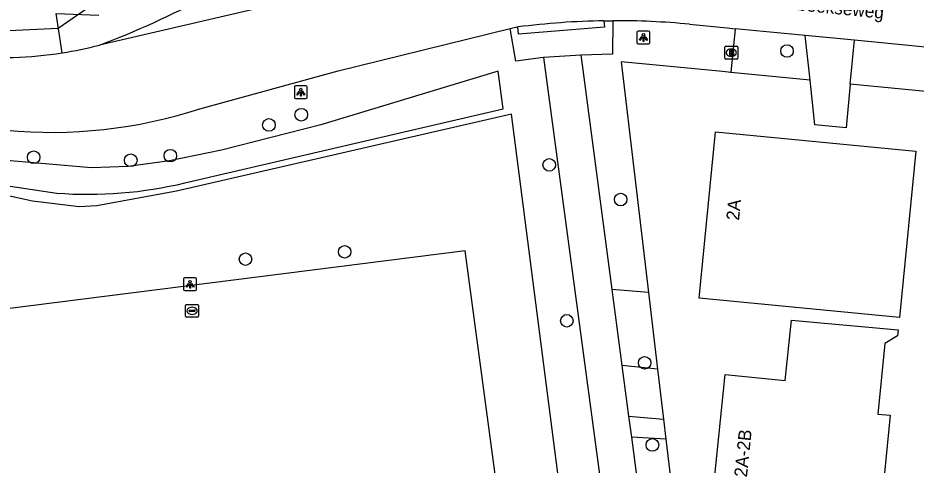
# Model space of a CAD drawing. Extents: x 162157 to 163165, y 378998 to 380775.
# Drawn here: x 162303.8 to 162373.7, y 380157.8 to 380192.5 of the extents above; entities that cross this region are included whole.
import ezdxf

# ---------------------------------------------------------------- set-up
doc = ezdxf.new("R2010")
doc.units = 0
for name, color, linetype in [('IMGEO_Boom', 7, 'Continuous'), ('IMGEO_Brandkraan', 7, 'Continuous'), ('IMGEO_Groenvoorziening', 7, 'Continuous'), ('IMGEO_Hek', 7, 'Continuous'), ('IMGEO_Lichtpunt', 7, 'Continuous'), ('IMGEO_Openbare_ruimte_label', 7, 'Continuous'), ('IMGEO_Pand', 7, 'Continuous'), ('IMGEO_Pand_nummerreeks', 7, 'Continuous'), ('IMGEO_Rijbaan_lokaal_gesloten', 7, 'Continuous'), ('IMGEO_Rijbaan_lokaal_open', 7, 'Continuous'), ('IMGEO_Voetpad_open', 7, 'Continuous'), ('IMGEO_Waterleidingput', 7, 'Continuous'), ('IMGEO_Waterloop', 7, 'Continuous')]:
    doc.layers.add(name, color=color, linetype=linetype)

msp = doc.modelspace()

# ---------------------------------------------------------------- linework, layer by layer
at = {"layer": 'IMGEO_Boom'}
for centre in [(162363.653, 380189.975), (162325.875, 380185.02), (162323.363, 380184.23), (162305.068, 380181.713), (162312.617, 380181.479), (162315.697, 380181.835), (162345.16, 380181.12), (162350.718, 380178.424), (162321.541, 380173.789), (162329.255, 380174.358), (162346.531, 380168.995), (162352.582, 380165.727), (162353.185, 380159.341)]:
    msp.add_circle(centre, 0.489, dxfattribs=at)
at = {"layer": 'IMGEO_Brandkraan'}
for p, q in [((162358.819, 380189.422), (162358.819, 380190.274)), ((162358.894, 380190.348), (162359.746, 380190.348)), ((162359.82, 380190.274), (162359.82, 380189.422)), ((162359.33, 380189.568), (162359.305, 380189.568)), ((162359.307, 380190.128), (162359.332, 380190.128)), ((162359.746, 380189.348), (162358.894, 380189.348))]:
    msp.add_line(p, q, dxfattribs=at)
for points in [[(162358.819, 380189.422), (162358.819, 380190.274)], [(162358.894, 380190.348), (162359.746, 380190.348)], [(162359.82, 380190.274), (162359.82, 380189.422)], [(162359.167, 380190.048), (162359.167, 380189.648), (162359.38, 380189.648)], [(162359.398, 380190.048), (162359.167, 380190.048)], [(162359.346, 380189.967), (162359.292, 380189.967), (162359.292, 380189.891)], [(162359.292, 380189.891), (162359.345, 380189.891)], [(162359.354, 380189.815), (162359.292, 380189.815), (162359.292, 380189.734)], [(162359.292, 380189.734), (162359.354, 380189.734)], [(162359.746, 380189.348), (162358.894, 380189.348)]]:
    msp.add_lwpolyline(points, dxfattribs=at)
for centre, radius, start, end in [((162358.896, 380190.272), 0.0765, 91.55205, 178.44795), ((162358.896, 380190.272), 0.0765, 91.55205, 178.44795), ((162359.744, 380190.272), 0.0765, 1.55205, 88.44795), ((162359.744, 380190.272), 0.0765, 1.55205, 88.44795), ((162359.347, 380189.929), 0.0379, 267.82845, 90.93552), ((162359.355, 380189.774), 0.0404, 269.87594, 90.50774), ((162359.386, 380189.899), 0.251, 268.66757, 293.53466), ((162359.402, 380189.903), 0.145, 59.4692, 91.53667), ((162359.427, 380189.95), 0.0922, 285.51372, 58.15012), ((162359.432, 380189.758), 0.105, 301.31148, 78.98903), ((162358.896, 380189.424), 0.0765, 181.55205, 268.44795), ((162358.896, 380189.424), 0.0765, 181.55205, 268.44795), ((162359.744, 380189.424), 0.0765, 271.55205, 358.44795), ((162359.744, 380189.424), 0.0765, 271.55205, 358.44795)]:
    msp.add_arc(centre, radius, start, end, dxfattribs=at)
for centre, major_axis, ratio, start_param, end_param in [((162359.306, 380189.848), (-0.387, 0.002), 0.722429, 4.712389, 7.853982), ((162359.331, 380189.848), (-0.39, 0.002), 0.717154, 1.570796, 4.712389)]:
    msp.add_ellipse(centre, major_axis=major_axis, ratio=ratio, start_param=start_param, end_param=end_param, dxfattribs=at)
at = {"layer": 'IMGEO_Groenvoorziening'}
for points in [[(162307.295, 380189.835), (162306.81, 380192.901), (162310.127, 380192.76)], [(162359.296, 380188.308), (162358.647, 380188.371), (162350.759, 380189.136), (162352.885, 380171.183)], [(162346.322, 380153.311), (162342.217, 380185.053), (162316.172, 380179.083), (162309.981, 380177.927), (162308.611, 380177.854), (162304.976, 380178.29), (162302.003, 380178.939), (162292.3, 380181.3), (162278.757, 380184.272), (162278.772, 380184.135)], [(162341.504, 380153.008), (162338.626, 380174.447), (162231.132, 380160.825)], [(162353.589, 380165.234), (162354.051, 380161.336)], [(162354.233, 380159.799), (162355.002, 380153.304)]]:
    msp.add_lwpolyline(points, dxfattribs=at)
at = {"layer": 'IMGEO_Hek'}
for points in [[(162325.53, 380205.107), (162316.565, 380198.358), (162306.984, 380191.725), (162299.257, 380191.374), (162294.601, 380191.534), (162271.637, 380197.316)], [(162342.217, 380185.053), (162316.172, 380179.083), (162309.981, 380177.927), (162308.611, 380177.854), (162304.976, 380178.29), (162302.003, 380178.939), (162292.3, 380181.3)], [(162346.322, 380153.311), (162342.217, 380185.053)]]:
    msp.add_lwpolyline(points, dxfattribs=at)
at = {"layer": 'IMGEO_Lichtpunt'}
for p, q in [((162351.985, 380191.432), (162351.985, 380190.625)), ((162351.985, 380191.432), (162351.985, 380190.625)), ((162352.887, 380191.527), (162352.079, 380191.527)), ((162352.887, 380191.527), (162352.079, 380191.527)), ((162352.981, 380190.625), (162352.981, 380191.432)), ((162352.981, 380190.625), (162352.981, 380191.432)), ((162352.079, 380190.531), (162352.887, 380190.531)), ((162352.079, 380190.531), (162352.887, 380190.531)), ((162325.339, 380187.178), (162325.339, 380186.371)), ((162325.339, 380187.178), (162325.339, 380186.371)), ((162326.241, 380187.273), (162325.433, 380187.273)), ((162326.241, 380187.273), (162325.433, 380187.273)), ((162326.335, 380186.371), (162326.335, 380187.178)), ((162326.335, 380186.371), (162326.335, 380187.178)), ((162325.433, 380186.277), (162326.241, 380186.277)), ((162325.433, 380186.277), (162326.241, 380186.277)), ((162316.729, 380172.244), (162316.729, 380171.437)), ((162316.729, 380172.244), (162316.729, 380171.437)), ((162317.631, 380172.339), (162316.823, 380172.339)), ((162317.631, 380172.339), (162316.823, 380172.339)), ((162317.725, 380171.437), (162317.725, 380172.244)), ((162317.725, 380171.437), (162317.725, 380172.244)), ((162316.823, 380171.343), (162317.631, 380171.343)), ((162316.823, 380171.343), (162317.631, 380171.343))]:
    msp.add_line(p, q, dxfattribs=at)
for points in [[(162352.359, 380191.096), (162352.398, 380191.068), (162352.21, 380190.806), (162352.172, 380190.833), (162352.359, 380191.096)], [(162352.461, 380191.048), (162352.508, 380191.048), (162352.508, 380190.726), (162352.461, 380190.726), (162352.461, 380191.048)], [(162352.571, 380191.068), (162352.609, 380191.095), (162352.796, 380190.833), (162352.757, 380190.805), (162352.571, 380191.068)], [(162325.713, 380186.842), (162325.752, 380186.814), (162325.564, 380186.552), (162325.526, 380186.579), (162325.713, 380186.842)], [(162325.815, 380186.794), (162325.862, 380186.794), (162325.862, 380186.472), (162325.815, 380186.472), (162325.815, 380186.794)], [(162325.925, 380186.814), (162325.963, 380186.841), (162326.15, 380186.579), (162326.111, 380186.551), (162325.925, 380186.814)], [(162317.103, 380171.908), (162317.142, 380171.88), (162316.954, 380171.618), (162316.916, 380171.645), (162317.103, 380171.908)], [(162317.205, 380171.86), (162317.252, 380171.86), (162317.252, 380171.538), (162317.205, 380171.538), (162317.205, 380171.86)], [(162317.315, 380171.88), (162317.353, 380171.907), (162317.54, 380171.645), (162317.501, 380171.617), (162317.315, 380171.88)]]:
    msp.add_lwpolyline(points, dxfattribs=at)
for centre in [(162352.484, 380191.23), (162325.838, 380186.976), (162317.228, 380172.042)]:
    msp.add_circle(centre, 0.0994, dxfattribs=at)
for centre, start, end in [((162352.079, 380191.432), 90, 180), ((162352.079, 380191.432), 90, 180), ((162352.887, 380191.432), 0, 90), ((162352.887, 380191.432), 0, 90), ((162352.079, 380190.625), 180, 270), ((162352.079, 380190.625), 180, 270), ((162352.887, 380190.625), 270, 0), ((162352.887, 380190.625), 270, 360), ((162325.433, 380187.178), 90, 180), ((162325.433, 380187.178), 90, 180), ((162326.241, 380187.178), 0, 90), ((162326.241, 380187.178), 0, 90), ((162325.433, 380186.371), 180, 270), ((162325.433, 380186.371), 180, 270), ((162326.241, 380186.371), 270, 0), ((162326.241, 380186.371), 270, 360), ((162316.823, 380172.244), 90, 180), ((162316.823, 380172.244), 90, 180), ((162317.631, 380172.244), 0, 90), ((162317.631, 380172.244), 0, 90), ((162316.823, 380171.437), 180, 270), ((162316.823, 380171.437), 180, 270), ((162317.631, 380171.437), 270, 0), ((162317.631, 380171.437), 270, 360)]:
    msp.add_arc(centre, 0.0946, start, end, dxfattribs=at)
at = {"layer": 'IMGEO_Pand'}
for points in [[(162372.403, 380169.242), (162356.818, 380170.763), (162358.08, 380183.688), (162373.671, 380182.198), (162372.403, 380169.242)], [(162371.671, 380161.643), (162370.324, 380147.858), (162366.184, 380148.262), (162365.979, 380146.162), (162361.805, 380146.57), (162362.337, 380152.428), (162357.628, 380152.906), (162358.838, 380164.825), (162363.514, 380164.35), (162363.991, 380169.046), (162372.294, 380168.296), (162372.247, 380167.838), (162371.264, 380167.24), (162370.725, 380161.731), (162371.671, 380161.643)]]:
    msp.add_lwpolyline(points, dxfattribs=at)
at = {"layer": 'IMGEO_Rijbaan_lokaal_gesloten'}
for points in [[(162351.924, 380198.488), (162349.145, 380198.355), (162345.414, 380198.175), (162329.976, 380195.039), (162310.176, 380190.435)], [(162317.977, 380185.472), (162328.735, 380188.436), (162342.118, 380191.718)], [(162342.118, 380191.718), (162342.53, 380191.819), (162342.628, 380191.832), (162342.726, 380191.844)], [(162349.415, 380192.326), (162350.112, 380192.332)], [(162356.076, 380192.058), (162359.007, 380191.772), (162359.614, 380191.713)], [(162365.074, 380191.181), (162359.614, 380191.713)], [(162368.891, 380190.809), (162365.074, 380191.181)], [(162379.916, 380189.734), (162368.891, 380190.809)]]:
    msp.add_lwpolyline(points, dxfattribs=at)
for centre, radius, start, end in [((162288.704, 380248.343), 61.76, 290.34479, 298.81046), ((162350.355, 380132.621), 59.712, 90.90236, 97.3407), ((162350.371, 380132.934), 59.398, 84.48886, 90.25024), ((162302.737, 380218.937), 29.456, 278.90108, 284.62756), ((162302.622, 380219.443), 29.974, 264.33401, 278.96829), ((162306.417, 380221.209), 37.56, 264.65655, 287.92526)]:
    msp.add_arc(centre, radius, start, end, dxfattribs=at)
at = {"layer": 'IMGEO_Rijbaan_lokaal_open'}
for points in [[(162347.629, 380189.663), (162344.718, 380189.464)], [(162347.629, 380189.663), (162347.729, 380188.908), (162350.037, 380171.422)], [(162344.718, 380189.464), (162344.822, 380188.69), (162350.587, 380145.671)], [(162350.037, 380171.422), (162350.816, 380165.525)], [(162350.816, 380165.525), (162351.338, 380161.569)], [(162351.338, 380161.569), (162351.553, 380159.939)], [(162351.553, 380159.939), (162352.394, 380153.567)]]:
    msp.add_lwpolyline(points, dxfattribs=at)
at = {"layer": 'IMGEO_Voetpad_open'}
for points in [[(162344.718, 380189.464), (162342.565, 380189.181), (162342.118, 380191.718)], [(162349.415, 380192.326), (162349.455, 380191.84), (162342.772, 380191.29), (162342.726, 380191.844)], [(162350.112, 380192.332), (162350.09, 380189.721), (162347.629, 380189.663)], [(162359.614, 380191.713), (162359.296, 380188.308)], [(162365.446, 380187.711), (162365.074, 380191.181)], [(162368.574, 380187.407), (162368.891, 380190.809)], [(162365.446, 380187.711), (162359.296, 380188.308)], [(162368.574, 380187.407), (162368.257, 380184.008), (162365.819, 380184.225), (162365.446, 380187.711)], [(162380.869, 380186.214), (162368.574, 380187.407)], [(162352.885, 380171.183), (162350.037, 380171.422)], [(162352.885, 380171.183), (162353.589, 380165.234)], [(162353.589, 380165.234), (162350.816, 380165.525)], [(162351.338, 380161.569), (162354.051, 380161.336)], [(162354.051, 380161.336), (162354.233, 380159.799)], [(162354.233, 380159.799), (162351.553, 380159.939)]]:
    msp.add_lwpolyline(points, dxfattribs=at)
at = {"layer": 'IMGEO_Waterleidingput'}
for p, q in [((162316.886, 380169.344), (162316.886, 380170.196)), ((162316.961, 380170.27), (162317.813, 380170.27)), ((162317.374, 380170.05), (162317.399, 380170.05)), ((162317.887, 380170.196), (162317.887, 380169.344)), ((162317.145, 380169.764), (162317.145, 380169.776)), ((162317.583, 380169.727), (162317.185, 380169.727)), ((162317.188, 380169.813), (162317.586, 380169.813)), ((162317.397, 380169.49), (162317.372, 380169.49)), ((162317.629, 380169.776), (162317.629, 380169.764)), ((162317.813, 380169.27), (162316.961, 380169.27))]:
    msp.add_line(p, q, dxfattribs=at)
for points in [[(162316.886, 380169.344), (162316.886, 380170.196)], [(162316.961, 380170.27), (162317.813, 380170.27)], [(162317.887, 380170.196), (162317.887, 380169.344)], [(162317.813, 380169.27), (162316.961, 380169.27)]]:
    msp.add_lwpolyline(points, dxfattribs=at)
for centre, radius, start, end in [((162316.963, 380170.194), 0.0765, 91.55205, 178.44795), ((162316.963, 380170.194), 0.0765, 91.55205, 178.44795), ((162317.811, 380170.194), 0.0765, 1.55205, 88.44795), ((162317.811, 380170.194), 0.0765, 1.55205, 88.44795), ((162316.963, 380169.346), 0.0765, 181.55205, 268.44795), ((162316.963, 380169.346), 0.0765, 181.55205, 268.44795), ((162317.185, 380169.773), 0.0403, 85.87752, 175.75265), ((162317.182, 380169.763), 0.0366, 178.93798, 274.71019), ((162317.586, 380169.77), 0.043, 264.86636, 352.45326), ((162317.59, 380169.775), 0.0386, 1.73085, 96.63898), ((162317.811, 380169.346), 0.0765, 271.55205, 358.44795), ((162317.811, 380169.346), 0.0765, 271.55205, 358.44795)]:
    msp.add_arc(centre, radius, start, end, dxfattribs=at)
for centre, major_axis, ratio, start_param, end_param in [((162317.373, 380169.77), (-0.387, 0.002), 0.722429, 4.712389, 7.853982), ((162317.398, 380169.77), (-0.39, 0.002), 0.717154, 1.570796, 4.712389)]:
    msp.add_ellipse(centre, major_axis=major_axis, ratio=ratio, start_param=start_param, end_param=end_param, dxfattribs=at)
at = {"layer": 'IMGEO_Waterloop'}
msp.add_lwpolyline([(162316.835, 380179.72), (162341.57, 380185.476), (162341.185, 380188.417), (162327.408, 380184.242), (162319.666, 380182.264), (162315.635, 380181.426), (162312.416, 380181.003), (162309.559, 380180.888), (162302.338, 380181.506), (162297.843, 380182.07), (162289.844, 380183.552), (162279.04, 380186.519), (162278.755, 380184.863), (162290.271, 380182.222), (162297.351, 380180.835), (162302.171, 380179.61), (162306.872, 380178.924)], dxfattribs=at)
msp.add_arc((162309.28, 380211.527), 32.692, 265.77515, 283.36081, dxfattribs=at)

# ---------------------------------------------------------------- texts
at = {"layer": 'IMGEO_Openbare_ruimte_label'}
msp.add_text('Achterbeekseweg', height=1, rotation=354.31792, dxfattribs=at).set_placement((162360.565, 380193.529))
at = {"layer": 'IMGEO_Pand_nummerreeks'}
for s, rotation, p in [('2A', 84.42533, (162359.917, 380176.768)), ('2A-2B', 84.20188, (162360.536, 380156.798))]:
    msp.add_text(s, height=1, rotation=rotation, dxfattribs=at).set_placement(p)

doc.saveas('drawing.dxf')
